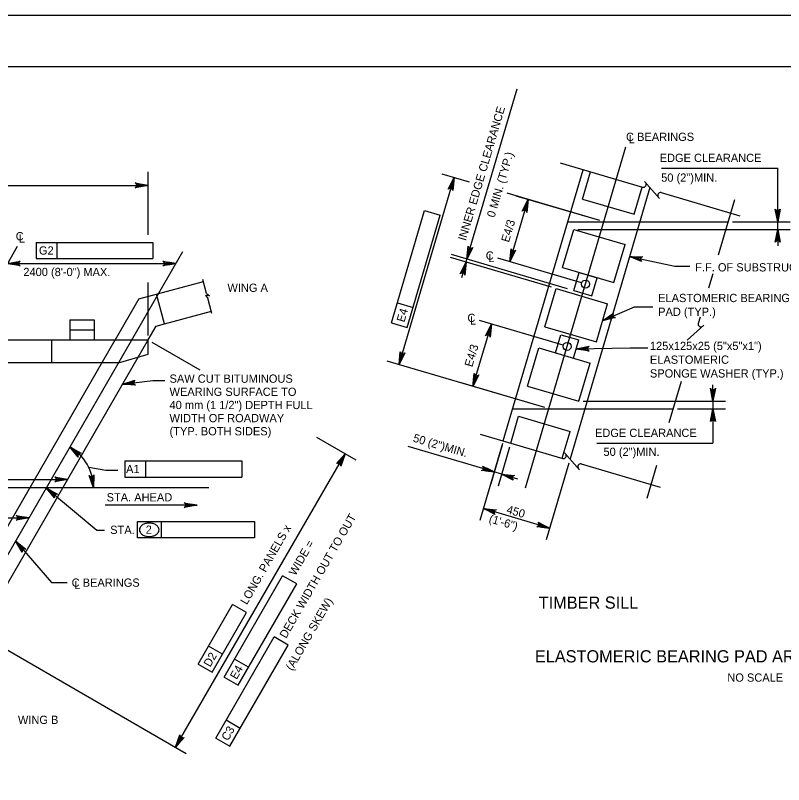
# Model space of a CAD drawing. Extents: x -8 to 75, y -110 to 0.
# Drawn here: x 48.5 to 59.67, y -11.19 to 0 of the extents above; entities that cross this region are included whole.
import ezdxf

# ---------------------------------------------------------------- set-up
doc = ezdxf.new("R2010")
doc.units = 0
for name, color, linetype in [('1', 7, 'Continuous'), ('2', 7, 'Continuous'), ('3', 7, 'Continuous'), ('4', 7, 'Continuous'), ('63', 7, 'Continuous'), ('7', 7, 'Continuous')]:
    doc.layers.add(name, color=color, linetype=linetype)

msp = doc.modelspace()

# ---------------------------------------------------------------- linework, layer by layer
at = {"layer": '1'}
msp.add_lwpolyline([(35.75, -21.25), (67.25, -21.25), (67.25, -0.75), (35.75, -0.75)], close=True, dxfattribs=at)
at = {"layer": '2'}
for p, q in [((50.296, -4.123), (51.234, -3.872)), ((50.296, -4.123), (49.951, -4.721)), ((50.666, -4.487), (50.55, -4.055)), ((50.666, -4.487), (51.349, -4.304)), ((49.291, -4.426), (49.291, -4.721)), ((49.291, -4.426), (49.645, -4.426)), ((49.645, -4.426), (49.645, -4.721)), ((50.429, -4.721), (50.545, -4.519)), ((50.545, -4.519), (50.666, -4.487)), ((42.482, -4.721), (50.429, -4.721)), ((47.486, -8.99), (49.951, -4.721)), ((50.285, -4.97), (50.429, -4.721)), ((50.429, -4.928), (50.429, -4.721)), ((48.083, -8.784), (50.285, -4.97)), ((49.999, -5.053), (50.429, -4.928)), ((49.999, -5.053), (42.911, -5.053))]:
    msp.add_line(p, q, dxfattribs=at)
at = {"layer": '3'}
for p, q in [((56.421, -2.145), (57.621, -2.499)), ((55.105, -2.427), (54.706, -2.309)), ((55.595, -6.19), (56.757, -2.244)), ((54.078, -5.079), (54.879, -2.36)), ((57.649, -2.416), (57.865, -2.661)), ((57.727, -2.505), (56.565, -6.451)), ((56.997, -2.984), (55.652, -2.588)), ((56.748, -2.671), (57.496, -2.892)), ((57.889, -2.578), (59.037, -2.915)), ((58.959, -2.683), (58.721, -3.489)), ((56.534, -3.002), (58.865, -3.002)), ((56.619, -3.112), (57.366, -3.332)), ((56.297, -3.954), (54.828, -3.522)), ((56.529, -3.975), (54.841, -3.478)), ((56.456, -3.666), (57.203, -3.886)), ((56.697, -3.737), (56.962, -3.815)), ((58.642, -3.758), (58.581, -3.967)), ((51.28, -4.047), (51.225, -3.842)), ((56.365, -3.974), (57.112, -4.195)), ((56.619, -4.002), (56.884, -4.079)), ((51.322, -4.078), (51.263, -4.074)), ((51.263, -4.074), (51.298, -4.113)), ((51.28, -4.047), (51.322, -4.078)), ((51.358, -4.337), (51.298, -4.113)), ((58.457, -4.388), (58.43, -4.479)), ((49.291, -4.574), (49.645, -4.574)), ((56.201, -4.528), (56.949, -4.749)), ((58.513, -4.506), (58.267, -4.723)), ((56.43, -4.644), (56.695, -4.721)), ((49.025, -4.721), (49.025, -5.053)), ((56.111, -4.837), (56.858, -5.057)), ((56.352, -4.908), (56.617, -4.986)), ((56.197, -5.703), (53.905, -5.029)), ((58.181, -5.324), (58.004, -5.926)), ((55.947, -5.391), (56.695, -5.611)), ((55.733, -5.721), (58.064, -5.721)), ((55.818, -5.831), (56.565, -6.052)), ((55.258, -6.091), (56.459, -6.444)), ((56.486, -6.362), (56.703, -6.607)), ((56.727, -6.523), (57.874, -6.861)), ((57.822, -6.544), (57.68, -7.024))]:
    msp.add_line(p, q, dxfattribs=at)
for points in [[(54.826, -2.47), (54.864, -2.481), (54.879, -2.36)], [(54.093, -4.959), (54.131, -4.97), (54.078, -5.079)]]:
    msp.add_lwpolyline(points, close=True, dxfattribs=at)
for centre, start, end in [((57.633, -2.459), 253.588, 43.588), ((57.882, -2.618), 78.9166, 221.4552), ((58.469, -4.49), 163.588, 313.588), ((56.47, -6.405), 253.588, 43.588), ((56.719, -6.564), 78.9166, 221.4552)]:
    msp.add_arc(centre, 0.0409, start, end, dxfattribs=at)
at = {"layer": '4'}
for p, q in [((55.1, -3.429), (55.795, -1.07)), ((55.917, -6.873), (57.379, -1.91)), ((57.895, -2.22), (59.585, -2.22)), ((59.585, -2.882), (59.585, -2.22)), ((50.429, -3.191), (50.429, -2.273)), ((42.482, -2.472), (50.429, -2.472)), ((55.688, -3.584), (55.955, -2.677)), ((56.997, -2.984), (55.783, -2.627)), ((53.969, -4.471), (54.45, -2.839)), ((54.196, -4.538), (54.677, -2.906)), ((54.45, -2.839), (54.677, -2.906)), ((58.927, -3.002), (59.765, -3.002)), ((59.585, -3.112), (59.585, -3.002)), ((56.681, -3.112), (59.765, -3.112)), ((59.585, -3.232), (59.585, -3.352)), ((48.8, -3.301), (50.5, -3.301)), ((48.8, -3.301), (48.8, -3.537)), ((49.102, -3.301), (49.102, -3.537)), ((50.5, -3.301), (50.5, -3.537)), ((48.526, -3.36), (46.786, -6.372)), ((50.929, -3.44), (47.169, -9.954)), ((48.8, -3.537), (50.5, -3.537)), ((55.053, -3.588), (55.066, -3.544)), ((56.73, -3.891), (55.516, -3.533)), ((48.382, -3.609), (50.832, -3.609)), ((58.087, -3.645), (58.308, -3.645)), ((55.02, -3.703), (54.986, -3.818)), ((50.429, -4.657), (50.429, -3.886)), ((54.055, -4.181), (54.282, -4.248)), ((57.495, -4.241), (57.769, -4.241)), ((53.969, -4.471), (54.196, -4.538)), ((56.463, -4.797), (55.249, -4.439)), ((55.154, -5.396), (55.421, -4.49)), ((50.483, -4.752), (51.181, -5.156)), ((57.44, -4.835), (57.695, -4.835)), ((50.057, -5.364), (50.498, -5.311)), ((50.498, -5.311), (50.674, -5.311)), ((56.197, -5.703), (54.982, -5.346)), ((58.644, -5.491), (58.644, -5.371)), ((56.758, -5.611), (58.824, -5.611)), ((58.644, -5.611), (58.644, -5.721)), ((58.127, -5.721), (58.824, -5.721)), ((58.644, -5.841), (58.644, -6.22)), ((52.88, -6.136), (53.449, -6.465)), ((55.584, -6.227), (55.255, -7.345)), ((55.577, -6.25), (55.412, -6.813)), ((56.954, -6.22), (58.644, -6.22)), ((50.828, -10.644), (53.293, -6.375)), ((55.462, -6.64), (54.211, -6.272)), ((55.685, -6.282), (55.519, -6.845)), ((50.089, -6.479), (51.79, -6.479)), ((50.089, -6.479), (50.089, -6.715)), ((50.391, -6.479), (50.391, -6.715)), ((51.79, -6.479), (51.79, -6.715)), ((49.566, -6.572), (49.812, -6.614)), ((56.547, -6.511), (56.218, -7.628)), ((49.812, -6.614), (49.991, -6.614)), ((55.57, -6.672), (55.462, -6.64)), ((55.57, -6.672), (55.8, -6.74)), ((41.431, -6.748), (49.258, -6.748)), ((50.089, -6.715), (51.79, -6.715)), ((51.311, -6.872), (39.62, -6.872)), ((48.948, -6.872), (49.682, -7.486)), ((51.142, -7.122), (49.806, -7.122)), ((56.269, -7.456), (55.306, -7.172)), ((41.347, -7.307), (48.697, -7.307)), ((50.276, -7.599), (50.276, -7.363)), ((50.276, -7.363), (51.977, -7.363)), ((50.626, -7.599), (50.626, -7.363)), ((51.977, -7.363), (51.977, -7.599)), ((49.682, -7.486), (49.796, -7.486)), ((51.977, -7.599), (50.276, -7.599)), ((48.503, -7.643), (49.024, -8.247)), ((51.536, -9.623), (52.386, -8.15)), ((52.59, -8.269), (52.386, -8.15)), ((49.024, -8.247), (49.254, -8.247)), ((51.74, -9.742), (52.59, -8.269)), ((51.157, -9.435), (51.657, -8.567)), ((51.862, -8.686), (51.657, -8.567)), ((51.361, -9.553), (51.862, -8.686)), ((48.018, -9.021), (50.984, -10.734)), ((51.413, -10.512), (52.264, -9.039)), ((52.468, -9.158), (52.264, -9.039)), ((51.512, -9.291), (51.308, -9.173)), ((51.618, -10.63), (52.468, -9.158)), ((51.891, -9.48), (51.687, -9.361)), ((51.157, -9.435), (51.361, -9.553)), ((51.536, -9.623), (51.74, -9.742)), ((51.769, -10.369), (51.564, -10.25)), ((51.413, -10.512), (51.618, -10.63))]:
    msp.add_line(p, q, dxfattribs=at)
for points in [[(50.429, -2.472), (50.242, -2.507), (50.256, -2.497), (50.264, -2.485), (50.266, -2.472), (50.264, -2.46), (50.256, -2.447), (50.242, -2.437), (50.429, -2.472), (50.256, -2.447), (50.264, -2.46), (50.429, -2.472), (50.266, -2.472), (50.264, -2.485), (50.429, -2.472), (50.256, -2.497)], [(54.879, -2.36), (54.86, -2.549), (54.854, -2.532), (54.844, -2.522), (54.833, -2.516), (54.82, -2.515), (54.806, -2.518), (54.793, -2.529), (54.879, -2.36), (54.806, -2.518), (54.82, -2.515), (54.879, -2.36), (54.833, -2.516), (54.844, -2.522), (54.879, -2.36), (54.854, -2.532)], [(55.955, -2.677), (55.936, -2.866), (55.931, -2.849), (55.921, -2.839), (55.909, -2.833), (55.897, -2.832), (55.883, -2.835), (55.869, -2.846), (55.955, -2.677), (55.883, -2.835), (55.897, -2.832), (55.955, -2.677), (55.909, -2.833), (55.921, -2.839), (55.955, -2.677), (55.931, -2.849)], [(59.585, -3.002), (59.55, -2.816), (59.56, -2.83), (59.573, -2.837), (59.585, -2.839), (59.598, -2.837), (59.61, -2.83), (59.62, -2.816), (59.585, -3.002), (59.61, -2.83), (59.598, -2.837), (59.585, -3.002), (59.585, -2.839), (59.573, -2.837), (59.585, -3.002), (59.56, -2.83)], [(59.585, -3.112), (59.62, -3.299), (59.61, -3.284), (59.598, -3.277), (59.585, -3.275), (59.573, -3.277), (59.56, -3.284), (59.55, -3.299), (59.585, -3.112), (59.56, -3.284), (59.573, -3.277), (59.585, -3.112), (59.585, -3.275), (59.598, -3.277), (59.585, -3.112), (59.61, -3.284)], [(55.066, -3.544), (55.086, -3.355), (55.091, -3.372), (55.101, -3.383), (55.112, -3.388), (55.125, -3.39), (55.139, -3.386), (55.153, -3.375), (55.066, -3.544), (55.139, -3.386), (55.125, -3.39), (55.066, -3.544), (55.112, -3.388), (55.101, -3.383), (55.066, -3.544), (55.091, -3.372)], [(55.688, -3.584), (55.707, -3.395), (55.713, -3.412), (55.723, -3.422), (55.734, -3.428), (55.747, -3.429), (55.761, -3.426), (55.774, -3.415), (55.688, -3.584), (55.761, -3.426), (55.747, -3.429), (55.688, -3.584), (55.734, -3.428), (55.723, -3.422), (55.688, -3.584), (55.713, -3.412)], [(48.382, -3.609), (48.568, -3.574), (48.554, -3.584), (48.547, -3.597), (48.544, -3.609), (48.547, -3.622), (48.554, -3.634), (48.568, -3.644), (48.382, -3.609), (48.554, -3.634), (48.547, -3.622), (48.382, -3.609), (48.544, -3.609), (48.547, -3.597), (48.382, -3.609), (48.554, -3.584)], [(50.832, -3.609), (50.645, -3.644), (50.66, -3.634), (50.667, -3.622), (50.669, -3.609), (50.667, -3.597), (50.66, -3.584), (50.645, -3.574), (50.832, -3.609), (50.66, -3.584), (50.667, -3.597), (50.832, -3.609), (50.669, -3.609), (50.667, -3.622), (50.832, -3.609), (50.66, -3.634)], [(57.432, -3.507), (58.087, -3.645)], [(57.432, -3.507), (57.622, -3.511), (57.605, -3.518), (57.596, -3.528), (57.591, -3.54), (57.59, -3.553), (57.595, -3.567), (57.607, -3.579), (57.432, -3.507), (57.595, -3.567), (57.59, -3.553), (57.432, -3.507), (57.591, -3.54), (57.596, -3.528), (57.432, -3.507), (57.605, -3.518)], [(55.053, -3.588), (55.034, -3.777), (55.029, -3.76), (55.019, -3.75), (55.008, -3.744), (54.995, -3.743), (54.981, -3.746), (54.967, -3.757), (55.053, -3.588), (54.981, -3.746), (54.995, -3.743), (55.053, -3.588), (55.008, -3.744), (55.019, -3.75), (55.053, -3.588), (55.029, -3.76)], [(57.041, -4.437), (57.501, -4.238)], [(57.041, -4.437), (57.198, -4.331), (57.189, -4.346), (57.187, -4.36), (57.19, -4.372), (57.197, -4.383), (57.209, -4.392), (57.226, -4.395), (57.041, -4.437), (57.209, -4.392), (57.197, -4.383), (57.041, -4.437), (57.19, -4.372), (57.187, -4.36), (57.041, -4.437), (57.189, -4.346)], [(55.421, -4.49), (55.402, -4.679), (55.397, -4.662), (55.387, -4.652), (55.375, -4.646), (55.363, -4.644), (55.349, -4.648), (55.335, -4.659), (55.421, -4.49), (55.349, -4.648), (55.363, -4.644), (55.421, -4.49), (55.375, -4.646), (55.387, -4.652), (55.421, -4.49), (55.397, -4.662)], [(54.078, -5.079), (54.097, -4.891), (54.103, -4.907), (54.112, -4.918), (54.124, -4.923), (54.136, -4.925), (54.151, -4.921), (54.164, -4.91), (54.078, -5.079), (54.151, -4.921), (54.136, -4.925), (54.078, -5.079), (54.124, -4.923), (54.112, -4.918), (54.078, -5.079), (54.103, -4.907)], [(56.656, -4.851), (56.842, -4.813), (56.828, -4.823), (56.821, -4.836), (56.819, -4.848), (56.821, -4.861), (56.829, -4.873), (56.843, -4.883), (56.656, -4.851), (56.829, -4.873), (56.821, -4.861), (56.656, -4.851), (56.819, -4.848), (56.821, -4.836), (56.656, -4.851), (56.828, -4.823)], [(56.656, -4.851), (57.44, -4.835)], [(55.154, -5.396), (55.173, -5.208), (55.179, -5.224), (55.189, -5.235), (55.2, -5.24), (55.213, -5.242), (55.227, -5.238), (55.24, -5.228), (55.154, -5.396), (55.227, -5.238), (55.213, -5.242), (55.154, -5.396), (55.2, -5.24), (55.189, -5.235), (55.154, -5.396), (55.179, -5.224)], [(50.057, -5.364), (50.238, -5.307), (50.225, -5.319), (50.219, -5.332), (50.219, -5.345), (50.222, -5.357), (50.231, -5.368), (50.247, -5.377), (50.057, -5.364), (50.231, -5.368), (50.222, -5.357), (50.057, -5.364), (50.219, -5.345), (50.219, -5.332), (50.057, -5.364), (50.225, -5.319)], [(58.644, -5.611), (58.609, -5.424), (58.619, -5.439), (58.632, -5.446), (58.644, -5.448), (58.657, -5.446), (58.669, -5.439), (58.679, -5.424), (58.644, -5.611), (58.669, -5.439), (58.657, -5.446), (58.644, -5.611), (58.644, -5.448), (58.632, -5.446), (58.644, -5.611), (58.619, -5.439)], [(58.644, -5.721), (58.679, -5.907), (58.669, -5.893), (58.657, -5.886), (58.644, -5.884), (58.632, -5.886), (58.619, -5.893), (58.609, -5.907), (58.644, -5.721), (58.619, -5.893), (58.632, -5.886), (58.644, -5.721), (58.644, -5.884), (58.657, -5.886), (58.644, -5.721), (58.669, -5.893)], [(49.292, -6.277), (49.458, -6.369), (49.441, -6.367), (49.427, -6.372), (49.417, -6.38), (49.411, -6.391), (49.409, -6.406), (49.414, -6.423), (49.292, -6.277), (49.409, -6.406), (49.411, -6.391), (49.292, -6.277), (49.417, -6.38), (49.427, -6.372), (49.292, -6.277), (49.441, -6.367)], [(53.293, -6.375), (53.23, -6.554), (53.229, -6.536), (53.222, -6.524), (53.212, -6.516), (53.2, -6.511), (53.185, -6.511), (53.17, -6.519), (53.293, -6.375), (53.185, -6.511), (53.2, -6.511), (53.293, -6.375), (53.212, -6.516), (53.222, -6.524), (53.293, -6.375), (53.229, -6.536)], [(55.462, -6.64), (55.274, -6.621), (55.29, -6.616), (55.301, -6.606), (55.306, -6.595), (55.308, -6.582), (55.304, -6.568), (55.294, -6.554), (55.462, -6.64), (55.304, -6.568), (55.308, -6.582), (55.462, -6.64), (55.306, -6.595), (55.301, -6.606), (55.462, -6.64), (55.29, -6.616)], [(49.635, -6.872), (49.571, -6.693), (49.583, -6.706), (49.597, -6.711), (49.609, -6.711), (49.621, -6.707), (49.633, -6.698), (49.64, -6.682), (49.635, -6.872), (49.633, -6.698), (49.621, -6.707), (49.635, -6.872), (49.609, -6.711), (49.597, -6.711), (49.635, -6.872), (49.583, -6.706)], [(55.57, -6.672), (55.759, -6.691), (55.742, -6.697), (55.731, -6.707), (55.726, -6.718), (55.724, -6.731), (55.728, -6.745), (55.739, -6.758), (55.57, -6.672), (55.728, -6.745), (55.724, -6.731), (55.57, -6.672), (55.726, -6.718), (55.731, -6.707), (55.57, -6.672), (55.742, -6.697)], [(49.258, -6.748), (49.072, -6.783), (49.086, -6.773), (49.094, -6.76), (49.096, -6.748), (49.094, -6.735), (49.086, -6.723), (49.072, -6.713), (49.258, -6.748), (49.086, -6.723), (49.094, -6.735), (49.258, -6.748), (49.096, -6.748), (49.094, -6.76), (49.258, -6.748), (49.086, -6.773)], [(48.948, -6.872), (49.113, -6.965), (49.096, -6.963), (49.082, -6.968), (49.073, -6.977), (49.066, -6.987), (49.064, -7.002), (49.069, -7.019), (48.948, -6.872), (49.064, -7.002), (49.066, -6.987), (48.948, -6.872), (49.073, -6.977), (49.082, -6.968), (48.948, -6.872), (49.096, -6.963)], [(51.142, -7.122), (50.955, -7.157), (50.969, -7.147), (50.977, -7.135), (50.979, -7.122), (50.977, -7.109), (50.969, -7.097), (50.955, -7.087), (51.142, -7.122), (50.969, -7.097), (50.977, -7.109), (51.142, -7.122), (50.979, -7.122), (50.977, -7.135), (51.142, -7.122), (50.969, -7.147)], [(55.306, -7.172), (55.494, -7.191), (55.478, -7.197), (55.467, -7.207), (55.462, -7.218), (55.46, -7.231), (55.464, -7.245), (55.475, -7.258), (55.306, -7.172), (55.464, -7.245), (55.46, -7.231), (55.306, -7.172), (55.462, -7.218), (55.467, -7.207), (55.306, -7.172), (55.478, -7.197)], [(48.697, -7.307), (48.511, -7.342), (48.525, -7.332), (48.532, -7.32), (48.534, -7.307), (48.532, -7.295), (48.525, -7.282), (48.511, -7.272), (48.697, -7.307), (48.525, -7.282), (48.532, -7.295), (48.697, -7.307), (48.534, -7.307), (48.532, -7.32), (48.697, -7.307), (48.525, -7.332)], [(56.269, -7.456), (56.08, -7.436), (56.097, -7.431), (56.107, -7.421), (56.113, -7.41), (56.114, -7.397), (56.111, -7.383), (56.1, -7.369), (56.269, -7.456), (56.111, -7.383), (56.114, -7.397), (56.269, -7.456), (56.113, -7.41), (56.107, -7.421), (56.269, -7.456), (56.097, -7.431)], [(48.503, -7.643), (48.651, -7.762), (48.634, -7.757), (48.62, -7.76), (48.609, -7.766), (48.601, -7.776), (48.596, -7.79), (48.598, -7.807), (48.503, -7.643), (48.596, -7.79), (48.601, -7.776), (48.503, -7.643), (48.609, -7.766), (48.62, -7.76), (48.503, -7.643), (48.634, -7.757)], [(50.828, -10.644), (50.891, -10.465), (50.893, -10.482), (50.9, -10.495), (50.91, -10.503), (50.922, -10.508), (50.936, -10.508), (50.952, -10.5), (50.828, -10.644), (50.936, -10.508), (50.922, -10.508), (50.828, -10.644), (50.91, -10.503), (50.9, -10.495), (50.828, -10.644), (50.893, -10.482)]]:
    msp.add_lwpolyline(points, dxfattribs=at)
for points in [[(55.902, -2.787), (55.941, -2.798), (55.955, -2.677)], [(59.565, -2.882), (59.605, -2.882), (59.585, -3.002)], [(59.565, -3.232), (59.605, -3.232), (59.585, -3.112)], [(55.081, -3.423), (55.12, -3.435), (55.066, -3.544)], [(55.703, -3.463), (55.741, -3.474), (55.688, -3.584)], [(57.432, -3.507), (57.547, -3.541), (57.551, -3.522)], [(50.718, -3.59), (50.718, -3.628), (50.832, -3.609)], [(55, -3.698), (55.039, -3.709), (55.053, -3.588)], [(57.041, -4.437), (57.155, -4.398), (57.147, -4.38)], [(55.368, -4.599), (55.407, -4.611), (55.421, -4.49)], [(50.172, -5.369), (50.168, -5.332), (50.057, -5.364)], [(55.169, -5.276), (55.207, -5.287), (55.154, -5.396)], [(58.624, -5.491), (58.664, -5.491), (58.644, -5.611)], [(58.624, -5.841), (58.664, -5.841), (58.644, -5.721)], [(53.216, -6.469), (53.25, -6.489), (53.293, -6.375)], [(55.353, -6.587), (55.342, -6.626), (55.462, -6.64)], [(55.691, -6.687), (55.679, -6.725), (55.57, -6.672)], [(55.427, -7.187), (55.415, -7.225), (55.306, -7.172)], [(56.159, -7.403), (56.148, -7.441), (56.269, -7.456)], [(50.871, -10.53), (50.906, -10.55), (50.828, -10.644)]]:
    msp.add_lwpolyline(points, close=True, dxfattribs=at)
for centre, radius, start, end in [((48.948, -6.872), 0.687, 0.0029, 59.9982), ((50.369, -7.481), 0.067, 148.5507, 180), ((50.369, -7.481), 0.067, 180, 211.4493), ((50.406, -7.504), 0.11, 124.109, 148.5507), ((50.43, -7.539), 0.153, 105.6708, 124.109), ((50.446, -7.595), 0.211, 90, 105.6708), ((50.446, -7.595), 0.211, 74.3292, 90), ((50.461, -7.539), 0.153, 55.891, 74.3292), ((50.485, -7.504), 0.11, 31.4493, 55.891), ((50.522, -7.481), 0.067, 0, 31.4493), ((50.522, -7.481), 0.067, 328.5507, 0), ((50.406, -7.459), 0.11, 211.4493, 235.891), ((50.43, -7.424), 0.153, 235.891, 254.3292), ((50.446, -7.368), 0.211, 254.3292, 270), ((50.446, -7.368), 0.211, 270, 285.6708), ((50.461, -7.424), 0.153, 285.6708, 304.109), ((50.485, -7.459), 0.11, 304.109, 328.5507)]:
    msp.add_arc(centre, radius, start, end, dxfattribs=at)
at = {"layer": '63'}
msp.add_lwpolyline([(34, -22), (68, -22), (68, 0), (34, 0)], close=True, dxfattribs=at)
at = {"layer": '7'}
for p, q in [((56.748, -2.671), (56.865, -2.276)), ((57.496, -2.892), (57.613, -2.496)), ((56.456, -3.666), (56.619, -3.112)), ((57.203, -3.886), (57.366, -3.332)), ((56.619, -4.002), (56.697, -3.737)), ((56.884, -4.079), (56.962, -3.815)), ((56.201, -4.528), (56.365, -3.974)), ((56.949, -4.749), (57.112, -4.195)), ((56.352, -4.908), (56.43, -4.644)), ((56.617, -4.986), (56.695, -4.721)), ((55.947, -5.391), (56.111, -4.837)), ((56.695, -5.611), (56.858, -5.057)), ((55.703, -6.222), (55.818, -5.831)), ((56.45, -6.442), (56.565, -6.052))]:
    msp.add_line(p, q, dxfattribs=at)
for centre in [(56.79, -3.908), (56.523, -4.815)]:
    msp.add_circle(centre, 0.059, dxfattribs=at)

# ---------------------------------------------------------------- texts
at = {"layer": '3'}
for s, p in [('TIMBER SILL', (56.11, -8.629)), ('ELASTOMERIC BEARING PAD ARRANGEMENTS', (56.054, -9.41))]:
    msp.add_text(s, height=0.17717, dxfattribs=at).set_placement(p)
at = {"layer": '4'}
for s, rotation, p in [('INNER EDGE CLEARANCE', 73.588, (55.05, -3.286)), ('0 MIN. (TYP.)', 73.588, (55.467, -2.948)), ('E4/3', 73.588, (55.676, -3.309)), ('G2', 359.9382, (48.841, -3.479)), ('2400 (8\'-0") MAX.', 359.9382, (48.615, -3.791)), ('E4', 73.5262, (54.155, -4.471)), ('E4/3', 73.588, (55.143, -5.122)), ('50 (2")MIN.', 343.588, (54.273, -6.197)), ('A1', 359.9382, (50.109, -6.657)), ('450', 343.588, (55.633, -7.237)), ('DECK WIDTH OUT TO OUT', 60, (52.436, -9.07)), ('(1\'-6")', 343.588, (55.376, -7.37)), ('LONG. PANELS x', 60, (51.865, -8.58)), ('WIDE =', 60, (52.572, -8.159)), ('(ALONG SKEW)', 60, (52.527, -9.54)), ('D2', 59.9382, (51.332, -9.487)), ('E4', 59.9382, (51.716, -9.667)), ('C3', 59.9382, (51.591, -10.56))]:
    msp.add_text(s, height=0.12, rotation=rotation, dxfattribs=at).set_placement(p)
for s, p in [('C BEARINGS', (57.38, -1.826)), ('L', (57.418, -1.862)), ('EDGE CLEARANCE', (57.869, -2.132)), ('50 (2")MIN.', (57.891, -2.419)), ('C', (48.504, -3.272)), ('L', (48.55, -3.306)), ('C', (55.34, -3.553)), ('L', (55.378, -3.589)), ('F.F. OF SUBSTRUCTURE', (58.386, -3.724)), ('WING A', (51.583, -4.021)), ('ELASTOMERIC BEARING', (57.847, -4.17)), ('PAD (TYP.)', (57.847, -4.37)), ('C', (55.073, -4.459)), ('L', (55.111, -4.496)), ('125x125x25 (5"x5"x1")', (57.727, -4.867)), ('ELASTOMERIC', (57.727, -5.067)), ('SPONGE WASHER (TYP.)', (57.727, -5.267)), ('SAW CUT BITUMINOUS', (50.741, -5.343)), ('WEARING SURFACE TO', (50.741, -5.534)), ('40 mm (1 1/2") DEPTH FULL', (50.741, -5.726)), ('WIDTH OF ROADWAY', (50.741, -5.917)), ('(TYP. BOTH SIDES)', (50.741, -6.108)), ('EDGE CLEARANCE', (56.928, -6.132)), ('50 (2")MIN.', (57.052, -6.407)), ('STA. AHEAD', (49.826, -7.069)), ('STA.', (49.878, -7.542)), ('2', (50.394, -7.54)), ('C BEARINGS', (49.317, -8.31)), ('L', (49.357, -8.344)), ('NO SCALE', (58.853, -9.691)), ('WING B', (48.536, -10.305))]:
    msp.add_text(s, height=0.12, dxfattribs=at).set_placement(p)

doc.saveas('drawing.dxf')
